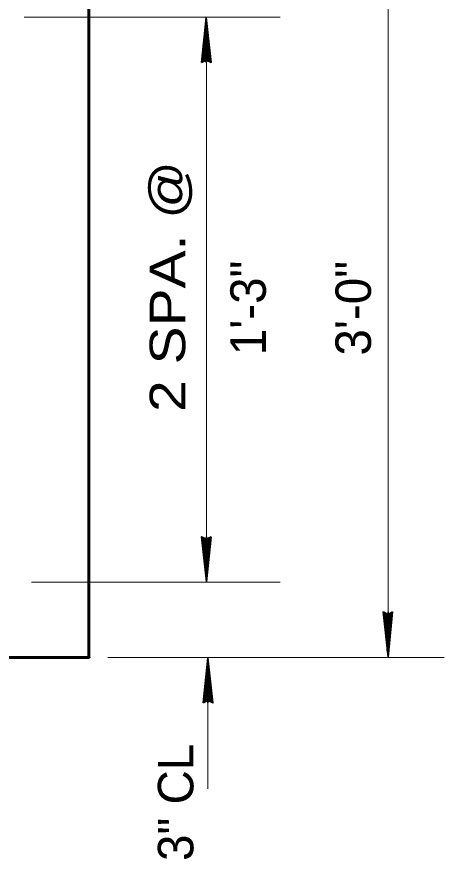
# Model space of a CAD drawing. Extents: x 4.49 to 7.69, y 0.28 to 2.27.
# Drawn here: x 5.4398 to 5.54, y 1.2641 to 1.4617 of the extents above; entities that cross this region are included whole.
import ezdxf

# ---------------------------------------------------------------- set-up
doc = ezdxf.new("R2010")
doc.units = 0
doc.header["$LTSCALE"] = 0.0033
doc.layers.add('1', color=7, linetype='Continuous', lineweight=35)

msp = doc.modelspace()

# ---------------------------------------------------------------- linework, layer by layer
at = {"layer": '1', "lineweight": 13}
for p, q in [((5.526833, 1.477417), (5.526833, 1.311417)), ((5.4415, 1.461667), (5.5015, 1.461667)), ((5.48425, 1.459583), (5.48425, 1.33)), ((5.443167, 1.329083), (5.5015, 1.329083)), ((5.456667, 1.311417), (5.457, 1.311417)), ((5.461083, 1.311417), (5.54, 1.311417)), ((5.484583, 1.280583), (5.484583, 1.301417))]:
    msp.add_line(p, q, dxfattribs=at)
at = {"layer": '1'}
for p, q in [((5.484167, 1.451), (5.484167, 1.461583)), ((5.483167, 1.45125), (5.484083, 1.459083)), ((5.483167, 1.45125), (5.484083, 1.459083)), ((5.48325, 1.45125), (5.484083, 1.459083)), ((5.483333, 1.45125), (5.484167, 1.459083)), ((5.483333, 1.45125), (5.484333, 1.459083)), ((5.484833, 1.451167), (5.484083, 1.4585)), ((5.485, 1.45125), (5.484167, 1.458583)), ((5.485083, 1.45125), (5.484333, 1.458583)), ((5.48525, 1.45125), (5.484417, 1.458583)), ((5.483167, 1.3395), (5.484, 1.332167)), ((5.483333, 1.3395), (5.484083, 1.332167)), ((5.483417, 1.3395), (5.48425, 1.332167)), ((5.483583, 1.339583), (5.484333, 1.33225)), ((5.485083, 1.3395), (5.484083, 1.331667)), ((5.48425, 1.33975), (5.48425, 1.329167)), ((5.485083, 1.3395), (5.48425, 1.331667)), ((5.48525, 1.3395), (5.484333, 1.331667)), ((5.48525, 1.3395), (5.484333, 1.331667)), ((5.485167, 1.3395), (5.484333, 1.331667)), ((5.526833, 1.322083), (5.526833, 1.3115)), ((5.52575, 1.321833), (5.526583, 1.3145)), ((5.525917, 1.321833), (5.526667, 1.3145)), ((5.526, 1.321833), (5.526833, 1.3145)), ((5.526167, 1.321917), (5.526917, 1.314583)), ((5.527667, 1.321833), (5.526667, 1.314)), ((5.527667, 1.321833), (5.526833, 1.314)), ((5.527833, 1.321833), (5.526917, 1.314)), ((5.527833, 1.321833), (5.526917, 1.314)), ((5.52775, 1.321833), (5.526917, 1.314)), ((5.484583, 1.30075), (5.484583, 1.311333)), ((5.483583, 1.301), (5.4845, 1.308833)), ((5.483583, 1.301), (5.4845, 1.308833)), ((5.483667, 1.301), (5.4845, 1.308833)), ((5.48375, 1.301), (5.484583, 1.308833)), ((5.48375, 1.301), (5.48475, 1.308833)), ((5.48525, 1.300917), (5.4845, 1.30825)), ((5.485417, 1.301), (5.484583, 1.308333)), ((5.4855, 1.301), (5.48475, 1.308333)), ((5.485667, 1.301), (5.484833, 1.308333))]:
    msp.add_line(p, q, dxfattribs=at)
at = {"layer": '1', "lineweight": 60}
msp.add_lwpolyline([(5.456667, 1.478083), (5.456667, 1.311417), (4.873333, 1.311417), (4.873333, 1.478083)], dxfattribs=at)
at = {"layer": '1'}
for points in [[(5.483083, 1.451), (5.484167, 1.461583), (5.485333, 1.451), (5.484167, 1.451583)], [(5.484083, 1.45175), (5.484, 1.456417), (5.484083, 1.456417), (5.484083, 1.4555), (5.484, 1.45175), (5.483917, 1.45475), (5.483833, 1.451583), (5.48375, 1.453833), (5.483667, 1.451583), (5.483917, 1.455083), (5.484083, 1.45975), (5.484333, 1.458833), (5.484333, 1.460083), (5.484333, 1.45175), (5.4845, 1.454167), (5.4845, 1.451583), (5.484083, 1.456917), (5.48475, 1.451583)], [(5.485333, 1.33975), (5.48425, 1.329167), (5.483083, 1.33975), (5.48425, 1.339167)], [(5.484333, 1.339), (5.484417, 1.334333), (5.484333, 1.334333), (5.484333, 1.33525), (5.484417, 1.339), (5.4845, 1.336), (5.484583, 1.339167), (5.484667, 1.336917), (5.48475, 1.339167), (5.4845, 1.335667), (5.484333, 1.331), (5.484083, 1.331917), (5.484083, 1.330667), (5.484083, 1.339), (5.483917, 1.336583), (5.483917, 1.339167), (5.484333, 1.333833), (5.483667, 1.339167)], [(5.527917, 1.322083), (5.526833, 1.3115), (5.525667, 1.322083), (5.526833, 1.3215)], [(5.526917, 1.321333), (5.527, 1.316667), (5.526917, 1.316667), (5.526917, 1.317583), (5.527, 1.321333), (5.527083, 1.318333), (5.527167, 1.3215), (5.52725, 1.31925), (5.527333, 1.3215), (5.527083, 1.318), (5.526917, 1.313333), (5.526667, 1.31425), (5.526667, 1.313), (5.526667, 1.321333), (5.5265, 1.318917), (5.5265, 1.3215), (5.526917, 1.316167), (5.52625, 1.3215)], [(5.4835, 1.30075), (5.484583, 1.311333), (5.48575, 1.30075), (5.484583, 1.301333)], [(5.4845, 1.3015), (5.484417, 1.306167), (5.4845, 1.306167), (5.4845, 1.30525), (5.484417, 1.3015), (5.484333, 1.3045), (5.48425, 1.301333), (5.484167, 1.303583), (5.484083, 1.301333), (5.484333, 1.304833), (5.4845, 1.3095), (5.48475, 1.308583), (5.48475, 1.309833), (5.48475, 1.3015), (5.484917, 1.303917), (5.484917, 1.301333), (5.4845, 1.306667), (5.485167, 1.301333)]]:
    msp.add_lwpolyline(points, close=True, dxfattribs=at)
for points in [[(5.484083, 1.45175), (5.483333, 1.451333), (5.483583, 1.451583), (5.483917, 1.45175), (5.483833, 1.452), (5.4835, 1.451833), (5.48425, 1.451667), (5.48475, 1.4515), (5.485167, 1.45125)], [(5.484333, 1.339), (5.485083, 1.339417), (5.484833, 1.339167), (5.4845, 1.339), (5.484583, 1.33875), (5.484917, 1.338917), (5.484167, 1.339083), (5.483667, 1.33925), (5.48325, 1.3395)], [(5.526917, 1.321333), (5.527667, 1.32175), (5.527417, 1.3215), (5.527083, 1.321333), (5.527167, 1.321083), (5.5275, 1.32125), (5.52675, 1.321417), (5.52625, 1.321583), (5.525833, 1.321833)], [(5.4845, 1.3015), (5.48375, 1.301083), (5.484, 1.301333), (5.484333, 1.3015), (5.48425, 1.30175), (5.483917, 1.301583), (5.484667, 1.301417), (5.485167, 1.30125), (5.485583, 1.301)]]:
    msp.add_lwpolyline(points, dxfattribs=at)

# ---------------------------------------------------------------- texts
at = {"layer": '1', "width": 1.2}
msp.add_text('2 SPA. @ ', height=0.008334, rotation=90, dxfattribs=at).set_placement((5.47925, 1.369))
at = {"layer": '1'}
for s, height, p in [('1\'-3"', 0.008334, (5.498167, 1.382333)), ('3\'-0"', 0.008333, (5.522833, 1.38225)), ('3" CL', 0.008334, (5.481167, 1.263667))]:
    msp.add_text(s, height=height, rotation=90, dxfattribs=at).set_placement(p)

doc.saveas('drawing.dxf')
